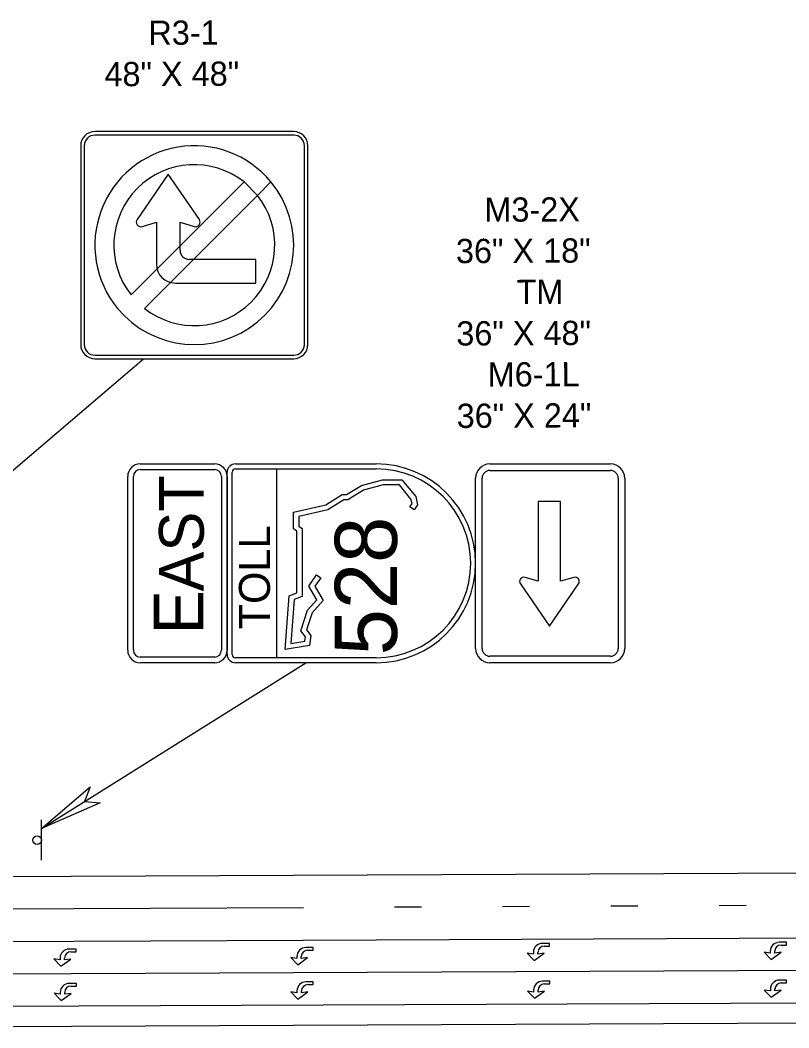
# Model space of a CAD drawing. Extents: x 582908 to 586040, y 1530940 to 1532988.
# Drawn here: x 584025 to 584469, y 1532406 to 1532988 of the extents above; entities that cross this region are included whole.
import ezdxf

# ---------------------------------------------------------------- set-up
doc = ezdxf.new("R2010")
doc.units = 0
for name, color, linetype in [('DirArrowsPavt', 7, 'Continuous'), ('LeaderLine_dp', 7, 'Continuous'), ('PMStripe6W', 7, 'Continuous'), ('PMStripe6W(10-30)', 7, 'Continuous'), ('PMStripe6Y', 7, 'Continuous'), ('PMStripe8W', 7, 'Continuous'), ('SignPanel', 7, 'Continuous'), ('SignSupport', 7, 'Continuous'), ('TextLabel', 7, 'Continuous')]:
    doc.layers.add(name, color=color, linetype=linetype)

msp = doc.modelspace()

# ---------------------------------------------------------------- linework, layer by layer
at = {"layer": 'DirArrowsPavt'}
for points in [[(584327.57, 1532453.21), (584330.7, 1532453.2), (584330.7, 1532454.77), (584326.53, 1532454.77)], [(584464.38, 1532453.82), (584467.5, 1532453.81), (584467.51, 1532455.37), (584463.34, 1532455.38)], [(584054.17, 1532449.89), (584057.29, 1532449.89), (584057.29, 1532451.45), (584053.13, 1532451.46)], [(584190.93, 1532450.75), (584194.06, 1532450.75), (584194.06, 1532452.31), (584189.9, 1532452.32)], [(584321.32, 1532449.57), (584321.32, 1532448.53), (584317.8, 1532449.06), (584321.83, 1532444.89)], [(584321.83, 1532444.89), (584327.57, 1532449.04), (584323.92, 1532448.53), (584323.92, 1532449.57)], [(584458.12, 1532450.18), (584458.12, 1532449.14), (584454.6, 1532449.67), (584458.63, 1532445.49)], [(584458.63, 1532445.49), (584464.37, 1532449.65), (584460.72, 1532449.13), (584460.73, 1532450.18)], [(584047.91, 1532446.26), (584047.91, 1532445.22), (584044.39, 1532445.74), (584048.42, 1532441.57)], [(584048.42, 1532441.57), (584054.16, 1532445.73), (584050.51, 1532445.21), (584050.51, 1532446.25)], [(584184.68, 1532447.12), (584184.68, 1532446.08), (584181.16, 1532446.6), (584185.19, 1532442.43)], [(584185.19, 1532442.43), (584190.93, 1532446.59), (584187.28, 1532446.07), (584187.28, 1532447.12)], [(584054.25, 1532430.06), (584057.38, 1532430.05), (584057.38, 1532431.61), (584053.21, 1532431.62)], [(584191.02, 1532430.92), (584194.15, 1532430.91), (584194.15, 1532432.48), (584189.98, 1532432.48)], [(584327.67, 1532431.35), (584330.8, 1532431.34), (584330.8, 1532432.9), (584326.63, 1532432.91)], [(584464.47, 1532431.95), (584467.6, 1532431.95), (584467.6, 1532433.51), (584463.44, 1532433.52)], [(584048, 1532426.42), (584048, 1532425.38), (584044.48, 1532425.91), (584048.51, 1532421.73)], [(584048.51, 1532421.73), (584054.25, 1532425.89), (584050.6, 1532425.38), (584050.6, 1532426.42)], [(584184.77, 1532427.28), (584184.76, 1532426.24), (584181.25, 1532426.77), (584185.28, 1532422.6)], [(584185.28, 1532422.6), (584191.02, 1532426.75), (584187.37, 1532426.24), (584187.37, 1532427.28)], [(584321.41, 1532427.71), (584321.41, 1532426.67), (584317.9, 1532427.2), (584321.93, 1532423.02)], [(584321.93, 1532423.02), (584327.66, 1532427.18), (584324.02, 1532426.66), (584324.02, 1532427.71)], [(584458.22, 1532428.32), (584458.22, 1532427.28), (584454.7, 1532427.8), (584458.73, 1532423.63)], [(584458.73, 1532423.63), (584464.47, 1532427.79), (584460.82, 1532427.27), (584460.82, 1532428.31)]]:
    msp.add_lwpolyline(points, dxfattribs=at)
for centre, radius in [((584326.53, 1532449.57), 5.21), ((584463.33, 1532450.17), 5.21), ((584464.37, 1532450.17), 3.65), ((584053.12, 1532446.25), 5.21), ((584054.16, 1532446.25), 3.65), ((584189.89, 1532447.11), 5.21), ((584190.93, 1532447.11), 3.65), ((584327.57, 1532449.56), 3.65), ((584053.21, 1532426.41), 5.21), ((584189.97, 1532427.28), 5.21), ((584191.02, 1532427.27), 3.65), ((584326.62, 1532427.7), 5.21), ((584327.66, 1532427.7), 3.65), ((584463.43, 1532428.31), 5.21), ((584464.47, 1532428.31), 3.65), ((584054.25, 1532426.41), 3.65)]:
    msp.add_arc(centre, radius, 89.90326, 179.90326, dxfattribs=at)
at = {"layer": 'LeaderLine_dp'}
for p, q in [((583770.98, 1532514.7), (584096.08, 1532792.5)), ((584037.19, 1532521.1), (584189.87, 1532616.9)), ((584037.19, 1532521.1), (584065.26, 1532545.19)), ((584065.26, 1532545.19), (584061.97, 1532536.65)), ((584071.09, 1532535.89), (584037.19, 1532521.1)), ((584061.97, 1532536.65), (584071.09, 1532535.89))]:
    msp.add_line(p, q, dxfattribs=at)
at = {"layer": 'PMStripe6W'}
for p, q in [((583998.69, 1532474.6), (584188.53, 1532475.44)), ((584188.62, 1532456.69), (584842.51, 1532459.59)), ((583998.77, 1532455.85), (584188.62, 1532456.69)), ((583998.86, 1532437.1), (584764.47, 1532440.5))]:
    msp.add_line(p, q, dxfattribs=at)
at = {"layer": 'PMStripe6W(10-30)'}
for p, q in [((584256.67, 1532475.75), (584241.04, 1532475.68)), ((584319.16, 1532476.02), (584303.54, 1532475.95)), ((584381.66, 1532476.3), (584366.04, 1532476.23)), ((584444.16, 1532476.58), (584428.54, 1532476.51))]:
    msp.add_line(p, q, dxfattribs=at)
at = {"layer": 'PMStripe6Y'}
for p, q in [((583918.07, 1532417.99), (584815.89, 1532421.97)), ((583847.49, 1532405.96), (584975.54, 1532410.96))]:
    msp.add_line(p, q, dxfattribs=at)
at = {"layer": 'PMStripe8W'}
msp.add_line((583998.61, 1532493.35), (584975.15, 1532497.68), dxfattribs=at)
at = {"layer": 'SignPanel'}
for p, q in [((584182.87, 1532923.75), (584068.03, 1532923.75)), ((584182.87, 1532921.7), (584068.03, 1532921.7)), ((584059.83, 1532915.55), (584059.83, 1532800.71)), ((584061.88, 1532915.55), (584061.88, 1532800.71)), ((584189.02, 1532800.71), (584189.02, 1532915.55)), ((584191.07, 1532800.71), (584191.07, 1532915.55)), ((584110.41, 1532899.14), (584092.44, 1532873.01)), ((584128.39, 1532873.01), (584110.41, 1532899.14)), ((584088.94, 1532829.36), (584154.22, 1532894.63)), ((584161.96, 1532886.9), (584154.22, 1532894.63)), ((584161.96, 1532886.9), (584169.74, 1532894.68)), ((584161.96, 1532886.9), (584096.68, 1532821.62)), ((584095.5, 1532868.85), (584103.57, 1532871.37)), ((584103.57, 1532871.37), (584103.57, 1532847.19)), ((584117.25, 1532855.18), (584117.25, 1532871.37)), ((584117.25, 1532871.37), (584125.32, 1532868.85)), ((584161, 1532849.93), (584122.5, 1532849.93)), ((584161, 1532836.25), (584161, 1532849.93)), ((584114.51, 1532836.25), (584161, 1532836.25)), ((584068.03, 1532794.55), (584182.87, 1532794.55)), ((584068.03, 1532792.5), (584182.87, 1532792.5)), ((584222.08, 1532719.34), (584234.1, 1532722.63)), ((584234.1, 1532722.63), (584245.33, 1532722.63)), ((584245.33, 1532722.63), (584253.36, 1532712.84)), ((584213.29, 1532714.01), (584222.08, 1532719.34)), ((584223.27, 1532716.57), (584214.13, 1532711.02)), ((584234.5, 1532719.64), (584223.27, 1532716.57)), ((584243.91, 1532719.64), (584234.5, 1532719.64)), ((584250.61, 1532711.47), (584243.91, 1532719.64)), ((584201.42, 1532708.11), (584210.9, 1532714.01)), ((584211.76, 1532711.02), (584202.58, 1532705.31)), ((584210.9, 1532714.01), (584213.29, 1532714.01)), ((584214.13, 1532711.02), (584211.76, 1532711.02)), ((584251.25, 1532708.79), (584250.61, 1532711.47)), ((584253.36, 1532712.84), (584254.47, 1532708.18)), ((584324.13, 1532709.99), (584324.13, 1532663.94)), ((584337.05, 1532709.99), (584324.13, 1532709.99)), ((584337.05, 1532663.94), (584337.05, 1532709.99)), ((584182.78, 1532703.78), (584201.42, 1532708.11)), ((584202.58, 1532705.31), (584185.77, 1532701.4)), ((584249.97, 1532706.94), (584251.25, 1532708.79)), ((584252.43, 1532705.23), (584249.97, 1532706.94)), ((584254.47, 1532708.18), (584252.43, 1532705.23)), ((584182.78, 1532694.21), (584182.78, 1532703.78)), ((584185.77, 1532701.4), (584185.77, 1532695.8)), ((584184.76, 1532692.87), (584182.78, 1532694.21)), ((584184.76, 1532657.3), (584184.76, 1532692.87)), ((584185.77, 1532695.8), (584187.75, 1532694.46)), ((584187.75, 1532694.46), (584187.75, 1532655.25)), ((584191.59, 1532661.15), (584195.97, 1532667.63)), ((584198.45, 1532665.95), (584195.12, 1532661.04)), ((584195.97, 1532667.63), (584198.45, 1532665.95)), ((584324.13, 1532663.94), (584316.53, 1532666.21)), ((584344.65, 1532666.21), (584337.05, 1532663.94)), ((584196.27, 1532653.19), (584191.59, 1532661.15)), ((584195.12, 1532661.04), (584199.97, 1532652.78)), ((584313.8, 1532662.46), (584330.59, 1532638.01)), ((584330.59, 1532638.01), (584347.38, 1532662.46)), ((584177.91, 1532624.55), (584180.3, 1532655.56)), ((584180.3, 1532655.56), (584184.76, 1532657.3)), ((584183.14, 1532653.46), (584181.18, 1532628.09)), ((584187.75, 1532655.25), (584183.14, 1532653.46)), ((584190.83, 1532647.32), (584196.27, 1532653.19)), ((584199.97, 1532652.78), (584193.47, 1532645.76)), ((584186.93, 1532635.35), (584190.83, 1532647.32)), ((584193.47, 1532645.76), (584190.27, 1532635.94)), ((584189.71, 1532631.83), (584186.93, 1532635.35)), ((584190.27, 1532635.94), (584192.83, 1532632.7)), ((584181.18, 1532628.09), (584189.4, 1532629.37)), ((584189.4, 1532629.37), (584189.71, 1532631.83)), ((584192.83, 1532632.7), (584192.09, 1532626.76)), ((584192.09, 1532626.76), (584177.91, 1532624.55))]:
    msp.add_line(p, q, dxfattribs=at)
for points in [[(584094.17, 1532731.74), (584137.24, 1532731.74)], [(584094.17, 1532728.45), (584137.24, 1532728.45)], [(584149.2, 1532731.74), (584230.55, 1532731.74)], [(584149.2, 1532728.87), (584230.55, 1532728.87)], [(584173.12, 1532619.77), (584173.12, 1532728.87)], [(584296.17, 1532731.74), (584365.9, 1532731.74)], [(584296.17, 1532727.98), (584365.9, 1532727.98)], [(584086.99, 1532624.07), (584086.99, 1532724.56)], [(584090.28, 1532624.07), (584090.28, 1532724.56)], [(584141.12, 1532724.56), (584141.12, 1532624.07)], [(584144.41, 1532621.68), (584144.41, 1532726.95)], [(584144.41, 1532724.56), (584144.41, 1532624.07)], [(584147.28, 1532621.68), (584147.28, 1532726.95)], [(584287.97, 1532625.1), (584287.97, 1532723.54)], [(584291.73, 1532625.1), (584291.73, 1532723.54)], [(584370.34, 1532723.54), (584370.34, 1532625.1)], [(584374.1, 1532723.54), (584374.1, 1532625.1)], [(584137.24, 1532620.19), (584094.17, 1532620.19)], [(584137.24, 1532616.9), (584094.17, 1532616.9)], [(584230.55, 1532619.77), (584149.2, 1532619.77)], [(584230.55, 1532616.9), (584149.2, 1532616.9)], [(584365.9, 1532620.66), (584296.17, 1532620.66)], [(584365.9, 1532616.9), (584296.17, 1532616.9)]]:
    msp.add_lwpolyline(points, dxfattribs=at)
for centre, radius, start, end in [((584068.03, 1532915.55), 8.2, 90, 180), ((584068.03, 1532915.55), 6.15, 90, 180), ((584182.87, 1532915.55), 8.2, 360, 90), ((584182.87, 1532915.55), 6.15, 360, 90), ((584125.45, 1532858.13), 57.42, 39.53499, 219.53501), ((584125.45, 1532858.13), 46.48, 51.75662, 218.24339), ((584125.45, 1532858.13), 57.42, 219.53501, 39.53499), ((584125.45, 1532858.13), 46.48, 231.75662, 38.24337), ((584094.69, 1532871.46), 2.73, 145.48536, 287.36264), ((584126.13, 1532871.46), 2.73, 252.63736, 34.51464), ((584122.5, 1532855.18), 5.25, 180, 270), ((584114.51, 1532847.19), 10.94, 180, 270), ((584068.03, 1532800.71), 8.2, 180, 270), ((584068.03, 1532800.71), 6.15, 180, 270), ((584182.87, 1532800.71), 6.15, 270, 360), ((584182.87, 1532800.71), 8.2, 270, 360), ((584094.17, 1532724.56), 7.18, 90, 180), ((584094.17, 1532724.56), 3.89, 90, 180), ((584137.24, 1532724.56), 7.18, 0, 90), ((584137.24, 1532724.56), 3.89, 0, 90), ((584149.2, 1532726.95), 4.79, 90, 180), ((584149.2, 1532726.95), 1.91, 90, 180), ((584230.55, 1532674.32), 57.42, 270, 90), ((584230.55, 1532674.32), 54.55, 270, 90), ((584296.17, 1532723.54), 8.2, 90, 180), ((584296.17, 1532723.54), 4.44, 90.0544, 180), ((584365.9, 1532723.54), 8.2, 360, 90), ((584365.9, 1532723.54), 4.44, 360, 90), ((584315.82, 1532663.85), 2.46, 73.35571, 214.48807), ((584345.36, 1532663.85), 2.46, 325.51192, 106.64431), ((584094.17, 1532624.07), 7.18, 180, 270), ((584094.17, 1532624.07), 3.89, 180, 270), ((584137.24, 1532624.07), 7.18, 270, 0), ((584137.24, 1532624.07), 3.89, 270, 0), ((584296.17, 1532625.1), 8.2, 180, 270), ((584296.17, 1532625.1), 4.44, 180, 269.9456), ((584365.9, 1532625.1), 8.2, 270, 360), ((584365.9, 1532625.1), 4.44, 270, 360), ((584149.2, 1532621.68), 4.79, 180, 270), ((584149.2, 1532621.68), 1.91, 180, 270)]:
    msp.add_arc(centre, radius, start, end, dxfattribs=at)
at = {"layer": 'SignSupport'}
msp.add_line((584037.19, 1532502.81), (584037.19, 1532526.09), dxfattribs=at)
msp.add_circle((584034.69, 1532514.45), 2.49, dxfattribs=at)

# ---------------------------------------------------------------- texts
at = {"layer": 'SignPanel'}
for s, height, p in [('AST', 25.839, (584130.92, 1532658.06)), ('528', 35.889, (584242.52, 1532621.18)), ('TOLL', 17.944, (584169.18, 1532636.2)), ('E', 28.71, (584130.76, 1532633.24))]:
    msp.add_text(s, height=height, rotation=90, dxfattribs=at).set_placement(p)
at = {"layer": 'TextLabel'}
for s, p in [('R3-1', (584098.99, 1532973.82)), ('48" X 48"', (584073.59, 1532949.9)), ('M3-2X', (584293.06, 1532871.61)), ('36" X 18"', (584276.61, 1532847.73)), ('TM', (584311.66, 1532824.09)), ('36" X 48"', (584276.82, 1532800.13)), ('M6-1L', (584294.96, 1532776.41)), ('36" X 24"', (584277.03, 1532752.53))]:
    msp.add_text(s, height=14, rotation=0.25398, dxfattribs=at).set_placement(p)

doc.saveas('drawing.dxf')
